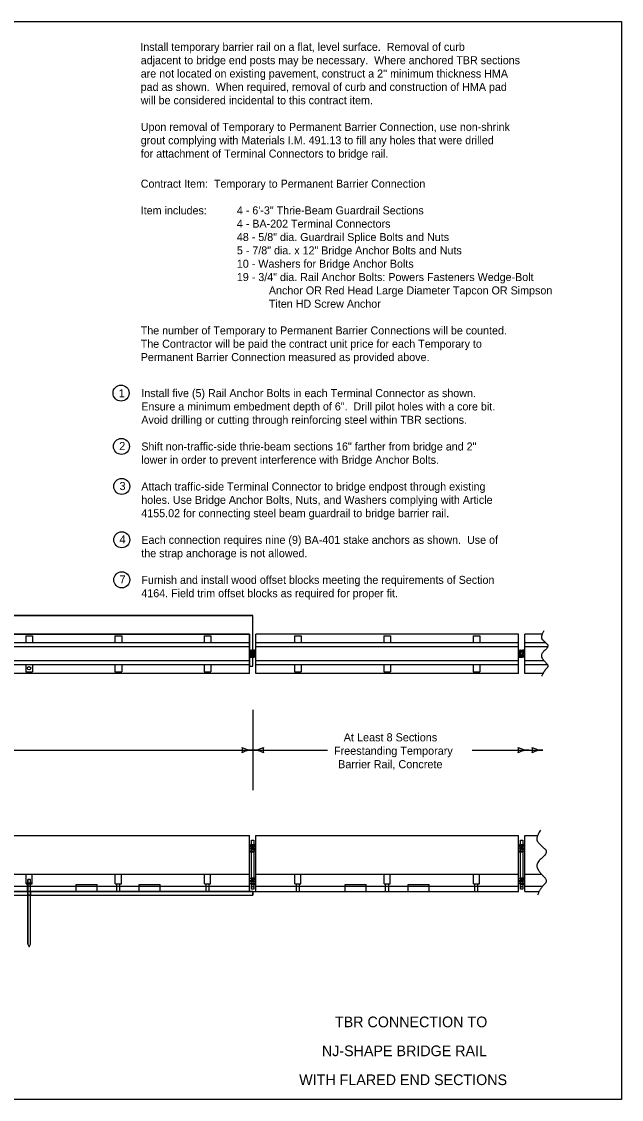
# Model space of a CAD drawing. Extents: x 10028 to 81668, y 3581 to 11018.
# Drawn here: x 19344 to 20468, y 7924 to 9944 of the extents above; entities that cross this region are included whole.
import ezdxf

# ---------------------------------------------------------------- set-up
doc = ezdxf.new("R2010")
doc.units = 0
for name, color, linetype in [('conPaving', 7, 'Continuous'), ('dsnCellsNorthArrow', 7, 'Continuous'), ('dsnTextTabulation', 7, 'Continuous'), ('Level 41', 7, 'Continuous'), ('Level 9', 7, 'Continuous'), ('SheetBorder', 7, 'Continuous')]:
    doc.layers.add(name, color=color, linetype=linetype)

msp = doc.modelspace()

# ---------------------------------------------------------------- linework, layer by layer
at = {"layer": 'conPaving'}
for p, q in [((19191.6, 8307.1), (19355.9, 8307.1)), ((19355.9, 8307.1), (19355.9, 8313.6)), ((19360.8, 8313.6), (19360.8, 8307.1)), ((19360.8, 8307.1), (19777.1, 8307.1)), ((19564.7, 8313.6), (19528.3, 8313.6)), ((19777.1, 8307.1), (19777.1, 8313.6))]:
    msp.add_line(p, q, dxfattribs=at)
for points in [[(19355.9, 8313.6), (19355.5, 8313.6), (19279.9, 8313.6)], [(19446.8, 8313.6), (19361.1, 8313.6), (19360.8, 8313.6)], [(19528.3, 8313.6), (19522.6, 8313.6), (19486.1, 8313.6), (19446.8, 8313.6)], [(19777.1, 8313.6), (19770.9, 8313.6), (19695.4, 8313.6), (19689.7, 8313.6), (19604.1, 8313.6), (19564.7, 8313.6)]]:
    msp.add_lwpolyline(points, dxfattribs=at)
at = {"layer": 'dsnTextTabulation'}
for p, q in [((19771.2, 8796.1), (19279.7, 8796.1)), ((19771.2, 8722.4), (19771.2, 8796.1)), ((20274.6, 8796.1), (19783.1, 8796.1)), ((19783.1, 8722.4), (19783.1, 8796.1)), ((20274.6, 8722.4), (20274.6, 8796.1)), ((20319.2, 8796.1), (20286.5, 8796.1)), ((20286.5, 8722.4), (20286.5, 8796.1)), ((19771.2, 8779.8), (19279.7, 8779.8)), ((19771.2, 8772.4), (19279.7, 8772.4)), ((20274.6, 8779.8), (19783.1, 8779.8)), ((20274.6, 8772.4), (19783.1, 8772.4)), ((20325.7, 8779.8), (20286.5, 8779.8)), ((20328.6, 8772.4), (20286.5, 8772.4)), ((19771.2, 8746.2), (19279.7, 8746.2)), ((19771.2, 8738.8), (19279.7, 8738.8)), ((20274.6, 8746.2), (19783.1, 8746.2)), ((20274.6, 8738.8), (19783.1, 8738.8)), ((20322.7, 8746.2), (20286.5, 8746.2)), ((20327.7, 8738.8), (20286.5, 8738.8)), ((19771.2, 8722.4), (19279.7, 8722.4)), ((20274.6, 8722.4), (19783.1, 8722.4)), ((20320.8, 8722.4), (20286.5, 8722.4)), ((19777.1, 8654.1), (19777.1, 8503.4)), ((18645.9, 8578.7), (19777.1, 8578.7)), ((19777.1, 8578.7), (19917, 8578.7)), ((20188, 8578.7), (20320.5, 8578.7)), ((19279.7, 8418.5), (19771.2, 8418.5)), ((19771.2, 8313.9), (19771.2, 8418.5)), ((19783.1, 8313.9), (19783.1, 8418.5)), ((19783.1, 8418.5), (20274.6, 8418.5)), ((20274.6, 8313.9), (20274.6, 8418.5)), ((20286.5, 8313.9), (20286.5, 8418.5)), ((20286.5, 8418.5), (20310.9, 8418.5)), ((19279.7, 8346.4), (19771.2, 8346.4)), ((19783.1, 8346.4), (20274.6, 8346.4)), ((20286.5, 8346.4), (20317.9, 8346.4)), ((19279.7, 8323.4), (19771.2, 8323.4)), ((19446.8, 8326.7), (19486.1, 8326.7)), ((19446.8, 8313.6), (19446.8, 8323.4)), ((19486.1, 8313.6), (19486.1, 8323.4)), ((19564.7, 8326.7), (19604.1, 8326.7)), ((19564.7, 8313.6), (19564.7, 8323.4)), ((19604.1, 8313.6), (19604.1, 8323.4)), ((19783.1, 8323.4), (20274.6, 8323.4)), ((19950.2, 8326.7), (19989.5, 8326.7)), ((19950.2, 8313.6), (19950.2, 8323.4)), ((19989.5, 8313.6), (19989.5, 8323.4)), ((20068.1, 8326.7), (20107.5, 8326.7)), ((20068.1, 8313.6), (20068.1, 8323.4)), ((20107.5, 8313.6), (20107.5, 8323.4)), ((20286.5, 8323.4), (20319.4, 8323.4)), ((19279.9, 8313.6), (19446.8, 8313.6)), ((19486.1, 8313.6), (19564.7, 8313.6)), ((19604.1, 8313.6), (19770.9, 8313.6)), ((19783.3, 8313.6), (19950.2, 8313.6)), ((19989.5, 8313.6), (20068.1, 8313.6)), ((20107.5, 8313.6), (20274.3, 8313.6)), ((20286.7, 8313.6), (20313.5, 8313.6))]:
    msp.add_line(p, q, dxfattribs=at)
for centre in [(19530.5, 9247.8), (19531.3, 9147.8), (19531.9, 9072.8), (19531.9, 8972.8), (19531.9, 8897.8)]:
    msp.add_circle(centre, 15, dxfattribs=at)
for centre, radius, start, end in [((19741.5, 8578.7), 16.4, 342.2666, 17.7333), ((19777.1, 8621.2), 42.5, 241.9275, 270), ((19741.5, 8578.7), 16.4, 342.2666, 17.7333), ((19777.1, 8621.2), 42.5, 241.9275, 270), ((19777.1, 8536.2), 42.5, 90, 118.0725), ((19777.1, 8536.2), 42.5, 90, 118.0725), ((19777.1, 8621.2), 42.5, 270, 298.0725), ((19777.1, 8536.2), 42.5, 61.9275, 90), ((19812.8, 8578.7), 16.4, 162.2666, 197.7334), ((20258.7, 8578.7), 16.4, 342.2666, 17.7333), ((20294.4, 8621.2), 42.5, 241.9275, 270), ((20294.4, 8536.2), 42.5, 90, 118.0725), ((20284.8, 8578.7), 16.4, 342.2666, 17.7333), ((20320.5, 8621.2), 42.5, 241.9275, 270), ((20320.5, 8536.2), 42.5, 90, 118.0725)]:
    msp.add_arc(centre, radius, start, end, dxfattribs=at)
at = {"layer": 'Level 41'}
for p, q in [((19352, 8793), (19364.6, 8793)), ((19352, 8793), (19352, 8779.8)), ((19364.6, 8793), (19364.6, 8779.8)), ((19519.1, 8793), (19531.7, 8793)), ((19519.1, 8793), (19519.1, 8779.8)), ((19531.7, 8793), (19531.7, 8779.8)), ((19686.3, 8793), (19686.3, 8779.8)), ((19686.3, 8793), (19698.8, 8793)), ((19698.8, 8793), (19698.8, 8779.8)), ((19855.4, 8793), (19868, 8793)), ((19855.4, 8793), (19855.4, 8779.8)), ((19868, 8793), (19868, 8779.8)), ((20022.5, 8793), (20035.1, 8793)), ((20022.5, 8793), (20022.5, 8779.8)), ((20035.1, 8793), (20035.1, 8779.8)), ((20189.7, 8793), (20189.7, 8779.8)), ((20189.7, 8793), (20202.2, 8793)), ((20202.2, 8793), (20202.2, 8779.8)), ((19771.2, 8766), (19775.1, 8766)), ((19771.2, 8763.6), (19775.1, 8763.6)), ((19771.2, 8755), (19775.1, 8755)), ((19771.2, 8752.6), (19775.1, 8752.6)), ((19783.1, 8766), (19779.1, 8766)), ((19783.1, 8763.6), (19779.1, 8763.6)), ((19783.1, 8755), (19779.1, 8755)), ((19783.1, 8752.6), (19779.1, 8752.6)), ((20274.6, 8766), (20278.5, 8766)), ((20274.6, 8763.6), (20278.5, 8763.6)), ((20274.6, 8755), (20278.5, 8755)), ((20274.6, 8752.6), (20278.5, 8752.6)), ((20286.5, 8766), (20282.5, 8766)), ((20286.5, 8763.6), (20282.5, 8763.6)), ((20286.5, 8755), (20282.5, 8755)), ((20286.5, 8752.6), (20282.5, 8752.6)), ((19352, 8738.8), (19352, 8725.5)), ((19364.6, 8738.8), (19364.6, 8725.5)), ((19519.1, 8738.8), (19519.1, 8725.5)), ((19531.7, 8738.8), (19531.7, 8725.5)), ((19686.3, 8738.8), (19686.3, 8725.5)), ((19698.8, 8738.8), (19698.8, 8725.5)), ((19855.4, 8738.8), (19855.4, 8725.5)), ((19868, 8738.8), (19868, 8725.5)), ((20022.5, 8738.8), (20022.5, 8725.5)), ((20035.1, 8738.8), (20035.1, 8725.5)), ((20189.7, 8738.8), (20189.7, 8725.5)), ((20202.2, 8738.8), (20202.2, 8725.5)), ((19352, 8725.5), (19364.6, 8725.5)), ((19519.1, 8725.5), (19531.7, 8725.5)), ((19686.3, 8725.5), (19698.8, 8725.5)), ((19855.4, 8725.5), (19868, 8725.5)), ((20022.5, 8725.5), (20035.1, 8725.5)), ((20189.7, 8725.5), (20202.2, 8725.5)), ((19771.2, 8399.9), (19779.7, 8399.9)), ((19771.2, 8397.7), (19779.7, 8397.7)), ((19771.2, 8390), (19779.7, 8390)), ((19771.2, 8387.9), (19779.7, 8387.9)), ((19774.6, 8394.9), (19783.1, 8394.9)), ((19774.6, 8392.8), (19783.1, 8392.8)), ((20274.6, 8399.9), (20283.1, 8399.9)), ((20274.6, 8397.7), (20283.1, 8397.7)), ((20274.6, 8390), (20283.1, 8390)), ((20274.6, 8387.9), (20283.1, 8387.9)), ((20278, 8394.9), (20286.5, 8394.9)), ((20278, 8392.8), (20286.5, 8392.8)), ((19352.6, 8327.8), (19352.6, 8346.4)), ((19364, 8327.8), (19364, 8346.4)), ((19519.8, 8327.8), (19519.8, 8346.4)), ((19531.1, 8327.8), (19531.1, 8346.4)), ((19686.9, 8327.8), (19686.9, 8346.4)), ((19698.2, 8327.8), (19698.2, 8346.4)), ((19856, 8327.8), (19856, 8346.4)), ((19867.4, 8327.8), (19867.4, 8346.4)), ((20023.2, 8327.8), (20023.2, 8346.4)), ((20034.5, 8327.8), (20034.5, 8346.4)), ((20190.3, 8327.8), (20190.3, 8346.4)), ((20201.6, 8327.8), (20201.6, 8346.4)), ((19352.6, 8327.8), (19364, 8327.8)), ((19355.5, 8313.6), (19355.5, 8327.8)), ((19361.1, 8313.6), (19361.1, 8327.8)), ((19519.8, 8327.8), (19531.1, 8327.8)), ((19522.6, 8313.6), (19522.6, 8327.8)), ((19528.3, 8313.6), (19528.3, 8327.8)), ((19686.9, 8327.8), (19698.2, 8327.8)), ((19689.7, 8313.6), (19689.7, 8327.8)), ((19695.4, 8313.6), (19695.4, 8327.8)), ((19771.2, 8334.3), (19779.7, 8334.3)), ((19771.2, 8332.2), (19779.7, 8332.2)), ((19774.6, 8339.2), (19783.1, 8339.2)), ((19774.6, 8337.1), (19783.1, 8337.1)), ((19774.6, 8329.4), (19783.1, 8329.4)), ((19774.6, 8327.3), (19783.1, 8327.3)), ((19856, 8327.8), (19867.4, 8327.8)), ((19858.9, 8313.6), (19858.9, 8327.8)), ((19864.5, 8313.6), (19864.5, 8327.8)), ((20023.2, 8327.8), (20034.5, 8327.8)), ((20026, 8313.6), (20026, 8327.8)), ((20031.7, 8313.6), (20031.7, 8327.8)), ((20190.3, 8327.8), (20201.6, 8327.8)), ((20193.1, 8313.6), (20193.1, 8327.8)), ((20198.8, 8313.6), (20198.8, 8327.8)), ((20274.6, 8334.3), (20283.1, 8334.3)), ((20274.6, 8332.2), (20283.1, 8332.2)), ((20278, 8339.2), (20286.5, 8339.2)), ((20278, 8337.1), (20286.5, 8337.1)), ((20278, 8329.4), (20286.5, 8329.4)), ((20278, 8327.3), (20286.5, 8327.3))]:
    msp.add_line(p, q, dxfattribs=at)
for centre, radius in [((19358.3, 8732.2), 3.15), ((19774.6, 8393.9), 1.06), ((19779.7, 8398.8), 1.06), ((19779.7, 8389), 1.06), ((20278, 8393.9), 1.06), ((20283.1, 8398.8), 1.06), ((20283.1, 8389), 1.06), ((19774.6, 8338.2), 1.06), ((19774.6, 8328.4), 1.06), ((19779.7, 8333.3), 1.06), ((20278, 8338.2), 1.06), ((20278, 8328.4), 1.06), ((20283.1, 8333.3), 1.06)]:
    msp.add_circle(centre, radius, dxfattribs=at)
for centre, radius, start, end in [((19779.1, 8759.3), 6.68, 90, 270), ((19779.1, 8759.3), 4.33, 90, 270), ((19775.1, 8759.3), 6.68, 270, 90), ((19775.1, 8759.3), 4.33, 270, 90), ((20282.5, 8759.3), 6.68, 90, 270), ((20282.5, 8759.3), 4.33, 90, 270), ((20278.5, 8759.3), 6.68, 270, 90), ((20278.5, 8759.3), 4.33, 270, 90)]:
    msp.add_arc(centre, radius, start, end, dxfattribs=at)
at = {"layer": 'Level 9'}
for p, q in [((17757.6, 8831), (19777.1, 8831)), ((19777.1, 8765.8), (19777.1, 8831)), ((19777.1, 8736), (19777.1, 8831)), ((19279.7, 8796.1), (19771.2, 8796.1)), ((19771.2, 8766), (19775.1, 8766)), ((19775.1, 8752.6), (19771.2, 8752.6)), ((19773, 8765.8), (19781.2, 8765.8)), ((19773, 8752.7), (19773, 8765.8)), ((19781.2, 8752.7), (19773, 8752.7)), ((19777.1, 8752.7), (19776.3, 8752.7)), ((19776.6, 8765.8), (19777.1, 8765.8)), ((19777.1, 8736), (19777.1, 8752.7)), ((19781.2, 8765.8), (19781.2, 8752.7)), ((20276.4, 8765.8), (20284.6, 8765.8)), ((20276.4, 8752.7), (20276.4, 8765.8)), ((20284.6, 8752.7), (20276.4, 8752.7)), ((20284.6, 8765.8), (20284.6, 8752.7)), ((19771.2, 8736), (19777.1, 8736)), ((19771.2, 8736), (19777.1, 8736)), ((19775.1, 8409.7), (19779.2, 8409.7)), ((19775.1, 8401.5), (19775.1, 8409.7)), ((19779.2, 8409.7), (19779.2, 8401.5)), ((20278.5, 8409.7), (20282.6, 8409.7)), ((20278.5, 8401.5), (20278.5, 8409.7)), ((20282.6, 8409.7), (20282.6, 8401.5)), ((19773, 8401.5), (19781.2, 8401.5)), ((19773, 8399.9), (19773, 8401.5)), ((19781.2, 8399.9), (19773, 8399.9)), ((19775.1, 8317.9), (19775.1, 8399.9)), ((19779.2, 8399.9), (19779.2, 8317.9)), ((19781.2, 8401.5), (19781.2, 8399.9)), ((20276.4, 8401.5), (20284.6, 8401.5)), ((20276.4, 8399.9), (20276.4, 8401.5)), ((20284.6, 8399.9), (20276.4, 8399.9)), ((20278.5, 8317.9), (20278.5, 8399.9)), ((20282.6, 8399.9), (20282.6, 8317.9)), ((20284.6, 8401.5), (20284.6, 8399.9)), ((19353.4, 8329.4), (19353.4, 8327.8)), ((19355.9, 8329.4), (19353.4, 8329.4)), ((19353.4, 8327.8), (19353.4, 8329.4)), ((19353.4, 8327.8), (19355.5, 8327.8)), ((19355.5, 8327.8), (19355.9, 8327.8)), ((19360.8, 8336), (19355.9, 8336)), ((19355.9, 8336), (19355.9, 8329.4)), ((19360.8, 8336), (19355.9, 8336)), ((19355.9, 8214.8), (19355.9, 8336)), ((19360.8, 8329.4), (19355.9, 8329.4)), ((19355.9, 8329.4), (19355.9, 8327.8)), ((19355.9, 8327.8), (19355.9, 8329.4)), ((19355.9, 8329.4), (19360.8, 8329.4)), ((19360.8, 8327.8), (19355.9, 8327.8)), ((19355.9, 8327.8), (19355.9, 8323.4)), ((19355.9, 8327.8), (19360.8, 8327.8)), ((19360.8, 8323.4), (19355.9, 8323.4)), ((19355.9, 8323.4), (19355.9, 8313.6)), ((19355.9, 8323.4), (19360.8, 8323.4)), ((19360.8, 8329.4), (19360.8, 8336)), ((19360.8, 8214.8), (19360.8, 8336)), ((19360.8, 8327.8), (19360.8, 8329.4)), ((19360.8, 8329.4), (19360.8, 8327.8)), ((19360.8, 8323.4), (19360.8, 8327.8)), ((19360.8, 8313.6), (19360.8, 8323.4)), ((19446.8, 8323.4), (19446.8, 8326.7)), ((19446.8, 8323.4), (19486.1, 8323.4)), ((19486.1, 8323.4), (19486.1, 8326.7)), ((19564.7, 8323.4), (19564.7, 8326.7)), ((19564.7, 8323.4), (19604.1, 8323.4)), ((19604.1, 8323.4), (19604.1, 8326.7)), ((19950.2, 8323.4), (19950.2, 8326.7)), ((19950.2, 8323.4), (19989.5, 8323.4)), ((19989.5, 8323.4), (19989.5, 8326.7)), ((20068.1, 8323.4), (20068.1, 8326.7)), ((20068.1, 8323.4), (20107.5, 8323.4)), ((20107.5, 8323.4), (20107.5, 8326.7)), ((17462, 8313.6), (20253.1, 8313.6)), ((17757.6, 8307.1), (19777.1, 8307.1)), ((19360.8, 8313.6), (19355.9, 8313.6)), ((19355.9, 8313.6), (19355.9, 8307.1)), ((19355.9, 8313.6), (19360.8, 8313.6)), ((19360.8, 8307.1), (19355.9, 8307.1)), ((19355.9, 8307.1), (19355.9, 8214.8)), ((19355.9, 8307.1), (19360.8, 8307.1)), ((19360.8, 8307.1), (19360.8, 8313.6)), ((19360.8, 8214.8), (19360.8, 8307.1)), ((19770.9, 8313.6), (19771.2, 8313.9)), ((19779.2, 8317.9), (19775.1, 8317.9)), ((19777.1, 8313.6), (19777.1, 8307.1)), ((19783.1, 8313.9), (19783.3, 8313.6)), ((20274.3, 8313.6), (20274.6, 8313.9)), ((20282.6, 8317.9), (20278.5, 8317.9)), ((20286.5, 8313.9), (20286.7, 8313.6)), ((19355.9, 8214.8), (19358.3, 8209.8)), ((19355.9, 8214.8), (19358.3, 8209.8)), ((19358.3, 8209.8), (19360.8, 8214.8)), ((19358.3, 8209.8), (19360.8, 8214.8))]:
    msp.add_line(p, q, dxfattribs=at)
for points in [[(19777.1, 8831), (18443, 8831), (18258, 8831), (18258, 8831)], [(19771.2, 8796.1), (19771.2, 8779.8), (19771.2, 8772.4), (19771.2, 8766)], [(19771.2, 8752.6), (19771.2, 8746.2), (19771.2, 8738.8), (19771.2, 8736)], [(19353.4, 8329.4), (19363.2, 8329.4), (19363.2, 8327.8), (19353.4, 8327.8)], [(19363.2, 8327.8), (19363.2, 8329.4), (19360.8, 8329.4)], [(19360.8, 8327.8), (19361.1, 8327.8), (19363.2, 8327.8)]]:
    msp.add_lwpolyline(points, dxfattribs=at)
for centre, radius in [((19777.1, 8759.3), 2.05), ((20280.5, 8759.3), 2.05), ((19777.1, 8322.9), 1.02), ((20280.5, 8322.9), 1.02)]:
    msp.add_circle(centre, radius, dxfattribs=at)
for start, end in [(77.6043, 90), (270, 280.2309)]:
    msp.add_arc((19775.1, 8759.3), 6.68, start, end, dxfattribs=at)
for points in [[(20322.2, 8801.9), (20314.9, 8790.7), (20323.9, 8781.3), (20332.9, 8773.2), (20315.7, 8758.6), (20320.5, 8747.5), (20332.4, 8736.4), (20323, 8727.8), (20318.3, 8717.5)], [(20315.7, 8428.4), (20305.2, 8412.3), (20318.2, 8398.8), (20331.1, 8387.1), (20306.5, 8366.1), (20313.2, 8350.1), (20330.5, 8334), (20316.9, 8321.7), (20310.2, 8306.9)]]:
    msp.add_open_spline(points, degree=2, dxfattribs=at)
at = {"layer": 'SheetBorder'}
msp.add_lwpolyline([(17332.5, 9944), (20467.5, 9944), (20467.5, 7924), (17332.5, 7924)], close=True, dxfattribs=at)

# ---------------------------------------------------------------- texts
at = {"layer": 'dsnCellsNorthArrow'}
for s, height, p in [('At Least 8 Sections', 15.2, (19947.5, 8595.1)), ('Freestanding Temporary', 15.2, (19929.2, 8569.9)), ('Barrier Rail, Concrete', 15.2, (19937, 8544.7)), ('TBR CONNECTION TO', 20, (19931.1, 8059.3)), ('NJ-SHAPE BRIDGE RAIL', 20, (19906.6, 8005.1)), ('WITH FLARED END SECTIONS', 20, (19864.1, 7950.9))]:
    msp.add_text(s, height=height, dxfattribs=at).set_placement(p)
at = {"layer": 'dsnTextTabulation'}
for s, p in [('1', (19526.1, 9239.9)), ('2', (19527.1, 9141)), ('3', (19527.7, 9066)), ('4', (19527.7, 8966)), ('7', (19527.7, 8891))]:
    msp.add_text(s, height=15.2, dxfattribs=at).set_placement(p)
at = {"layer": 'Level 9'}
for s, p in [('Install temporary barrier rail on a flat, level surface.  Removal of curb ', (19566.6, 9889.1)), ('adjacent to bridge end posts may be necessary.  Where anchored TBR sections ', (19567.4, 9864.1)), ("are not located on existing pavement, construct a 2'' minimum thickness HMA ", (19567.4, 9839.1)), ('pad as shown.  When required, removal of curb and construction of HMA pad ', (19567.3, 9814.1)), ('will be considered incidental to this contract item.', (19567.4, 9789.1)), ('Upon removal of Temporary to Permanent Barrier Connection, use non-shrink ', (19567.4, 9739.1)), ('grout complying with Materials I.M. 491.13 to fill any holes that were drilled ', (19567.4, 9714.1)), ('for attachment of Terminal Connectors to bridge rail.', (19567.4, 9689.1)), ('Contract Item:  Temporary to Permanent Barrier Connection', (19567.4, 9632.7)), ('Item includes:', (19567.4, 9582.7)), ('4 - 6\'-3" Thrie-Beam Guardrail Sections', (19747.4, 9582.7)), ('4 - BA-202 Terminal Connectors', (19747.4, 9557.7)), ('48 - 5/8" dia. Guardrail Splice Bolts and Nuts', (19747.4, 9532.7)), ('5 - 7/8" dia. x 12" Bridge Anchor Bolts and Nuts', (19747.4, 9507.7)), ('10 - Washers for Bridge Anchor Bolts', (19747.4, 9482.7)), ('19 - 3/4" dia. Rail Anchor Bolts: Powers Fasteners Wedge-Bolt', (19747.4, 9457.7)), ('Anchor OR Red Head Large Diameter Tapcon OR Simpson', (19807.4, 9432.7)), ('Titen HD Screw Anchor', (19807.4, 9407.7)), ('The number of Temporary to Permanent Barrier Connections will be counted.  ', (19567.4, 9357.7)), ('The Contractor will be paid the contract unit price for each Temporary to ', (19567.4, 9332.7)), ('Permanent Barrier Connection measured as provided above.', (19567.4, 9307.7)), ('Install five (5) Rail Anchor Bolts in each Terminal Connector as shown.  ', (19568.5, 9240.2)), ('Ensure a minimum embedment depth of 6".  Drill pilot holes with a core bit.  ', (19568.5, 9215.2)), ('Avoid drilling or cutting through reinforcing steel within TBR sections.', (19568.5, 9190.2)), ('Shift non-traffic-side thrie-beam sections 16" farther from bridge and 2" ', (19568.5, 9140.2)), ('lower in order to prevent interference with Bridge Anchor Bolts.', (19568.5, 9115.2)), ('Attach traffic-side Terminal Connector to bridge endpost through existing ', (19568.5, 9065.2)), ('holes. Use Bridge Anchor Bolts, Nuts, and Washers complying with Article ', (19568.5, 9040.2)), ('4155.02 for connecting steel beam guardrail to bridge barrier rail.', (19568.5, 9015.2)), ('Each connection requires nine (9) BA-401 stake anchors as shown.  Use of ', (19568.5, 8965.2)), ('the strap anchorage is not allowed.', (19568.5, 8940.2)), ('Furnish and install wood offset blocks meeting the requirements of Section ', (19568.5, 8890.2)), ('4164. Field trim offset blocks as required for proper fit.', (19568.5, 8865.2))]:
    msp.add_text(s, height=15, dxfattribs=at).set_placement(p)

doc.saveas('drawing.dxf')
